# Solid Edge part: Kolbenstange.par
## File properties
Username: bmolnar
Dokumentum tartalom típus: 0
Author: bmolnar
Last saved by: bmolnar
Revision: 81
Sűrűség: 0,000 kg/m^3
Pontosság: 0,990
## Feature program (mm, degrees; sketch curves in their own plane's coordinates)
base feature "unnamed BaseFeature 1"
sketch for "unnamed Protrusion 1" plane through (0, 0, -16.4) normal (0, 0, -1) x-axis (0, 1, 0)
  circle centre (0, 0) radius 16
extrude "unnamed Protrusion 1" add finite 18.25 along +normal
sketch for "Kihúzás_2" #1 plane through (0, 0, -16.4) normal (0, 0, -1) x-axis (0, 1, 0)
  circle centre (0, 0) radius 6
sketch for "Kihúzás_2" #2 plane through (0, 0, -16.4) normal (0, 0, -1) x-axis (0, 1, 0)
  circle centre (0, 0) radius 16
extrude "Kihúzás_2" add finite 12.35 along -normal
sketch for "Furat_1" plane through (0, 0, 33.9) normal (0, 0, 1) x-axis (1, 0, 0)
hole "Furat_1" diameter 4.92 finite  VBottomAngle = 118 deg
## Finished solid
Body 1: solid body, 16 faces, 22 edges, 8 vertices.
  Faces by surface: plane 8, cylinder 4, cone 2, torus 2
  Edges by curve: circle 12, line 6, curve on surface 2, ellipse 2
Bounding box of the edges (mm; curved faces can reach further): 32.000 x 32.000 x 71.050, from (-16, -16, -34.65) to (16, 16, 36.4).
Cylindrical faces by radius (mm): R2.46 x1, R3.125 x1, R6 x1, R16 x1
Conical faces (half-angle, radius in mm at the cone's reference point): 45 deg R3.225 x1, 59 deg R2.46 x1
Toroidal faces (ring radius, tube radius in mm): R2.725 r0.4 x1, R4.7 r1.3 x1
Planar faces by outward normal: +x 1, +z 3, -x 1, -z 1, oblique 2
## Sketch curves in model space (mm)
circle centre (0, 0, -16.4) radius 16
circle centre (0, 0, -16.4) radius 6
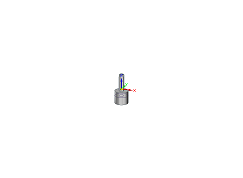
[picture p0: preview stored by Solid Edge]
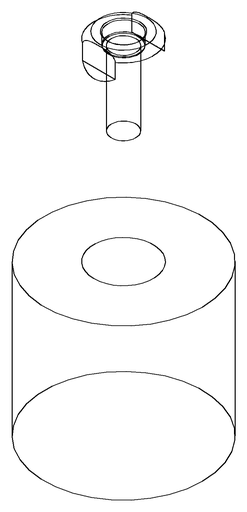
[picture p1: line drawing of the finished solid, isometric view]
